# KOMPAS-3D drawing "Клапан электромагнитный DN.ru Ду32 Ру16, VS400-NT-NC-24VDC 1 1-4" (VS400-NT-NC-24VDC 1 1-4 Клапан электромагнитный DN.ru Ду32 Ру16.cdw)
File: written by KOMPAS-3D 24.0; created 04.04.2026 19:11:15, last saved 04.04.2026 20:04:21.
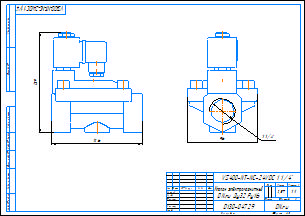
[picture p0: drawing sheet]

Document properties: c3d_UniqueCompID: ef56311e-7521-43dc-8291-0e6108b3d81d; Обозначение: VS400-ET-NC-220VAC 1; Наименование: Клапан электромагнитный DN.ru Ду25 Ру16; Автор: artio; Класс точности: c; Знак неуказанной шероховатости: Шероховатость не задана; Рассекать на разрезах: Да; c3d_UniqueCompID: ef56311e-7521-43dc-8291-0e6108b3d81d; Обозначение: VS400-ET-NC-220VAC 1-2; Наименование: Клапан электромагнитный DN.ru Ду15 Ру16; Автор: artio; Класс точности: c; Знак неуказанной шероховатости: Шероховатость не задана; Рассекать на разрезах: Да; c3d_UniqueCompID: ef56311e-7521-43dc-8291-0e6108b3d81d; Обозначение: VS400-ET-NC-220VAC 3-4; Наименование: Клапан электромагнитный DN.ru Ду20 Ру16; Автор: artio; Класс точности: c; Знак неуказанной шероховатости: Шероховатость не задана; Рассекать на разрезах: Да; c3d_UniqueCompID: ef56311e-7521-43dc-8291-0e6108b3d81d; Обозначение: VS400-ET-NC-220VAC 1 1-4; Наименование: Клапан электромагнитный DN.ru Ду32 Ру16; Автор: artio; Класс точности: c; Знак неуказанной шероховатости: Шероховатость не задана; Рассекать на разрезах: Да; c3d_UniqueCompID: ef56311e-7521-43dc-8291-0e6108b3d81d; Обозначение: VS400-ET-NC-220VAC 3-8; Наименование: Клапан электромагнитный DN.ru Ду10 Ру16; Автор: artio; Класс точности: c; Знак неуказанной шероховатости: Шероховатость не задана; Рассекать на разрезах: Да; Автор: artio; Форматы листов документа: A3; Полное имя файла: VS400-NT-NC-24VDC 1 1-4 Клапан электромагнитный DN.ru Ду32 Ру16.m3d; Масса: 2.569; Наименование: Клапан электромагнитный DN.ru Ду32 Ру16; Количество листов документа: 1; Примечание: D130-04729

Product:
- Body: Тело 1  | qty 1
    Масса: 4.144257
- Part/product: Клапан электромагнитный DN.ru Ду32 Ру16  | designation VS400-NT-NC-24VDC 1 1-4
    Масса: 2.569
    Раздел спецификации: Прочие изделия
    Примечание: D130-04729
    additional columns: ef56311e-7521-43dc-8291-0e6108b3d81d; VS400-ET-NC-220VAC 1 1-4; artio; c; Шероховатость не задана; Да

Views: Вид 1, Спереди
Referenced files in C:\Users\artio\OneDrive\Рабочий стол\Клапан электромагнитный DN.ru\VS400-ET-NC\VS400-ET-NC-24VDC\: VS400-ET-NC-24VDC 3-8 Клапан электромагнитный DN.ru Ду10 Ру16.m3d
Referenced files in C:\Users\artio\OneDrive\Рабочий стол\Клапан электромагнитный DN.ru\VS400-NT-NC\VS400-NT-NC-24VDC\: VS400-NT-NC-24VDC 1 1-4 Клапан электромагнитный DN.ru Ду32 Ру16.m3d
Referenced files in C:\Users\artio\OneDrive\Рабочий стол\Клапан электромагнитный DN.ru\VS400-ET-NC\: VS400-ET-NC-24VDC 3-8 Клапан электромагнитный DN.ru Ду10 Ру16.cdw
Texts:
  VS400-NT-NC-24VDC 1 1-4
  Клапан электромагнитный
  DN.ru Ду32 Ру16
  VS400-NT-NC-24VDC 1 1/4"
  VS400-NT-NC-24VDC 1 1/4"-
  Клапан электромагнитный DN.ru Ду32 Ру16
  VS400-NT-NC-24VDC 1 1-4 Клапан электромагнитный DN.ru Ду32 Ру16
Dimensions and other numbers on the sheet: 0; 3; 2; 4; 96; 1 1/4"; 1:1; 1; 2,57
